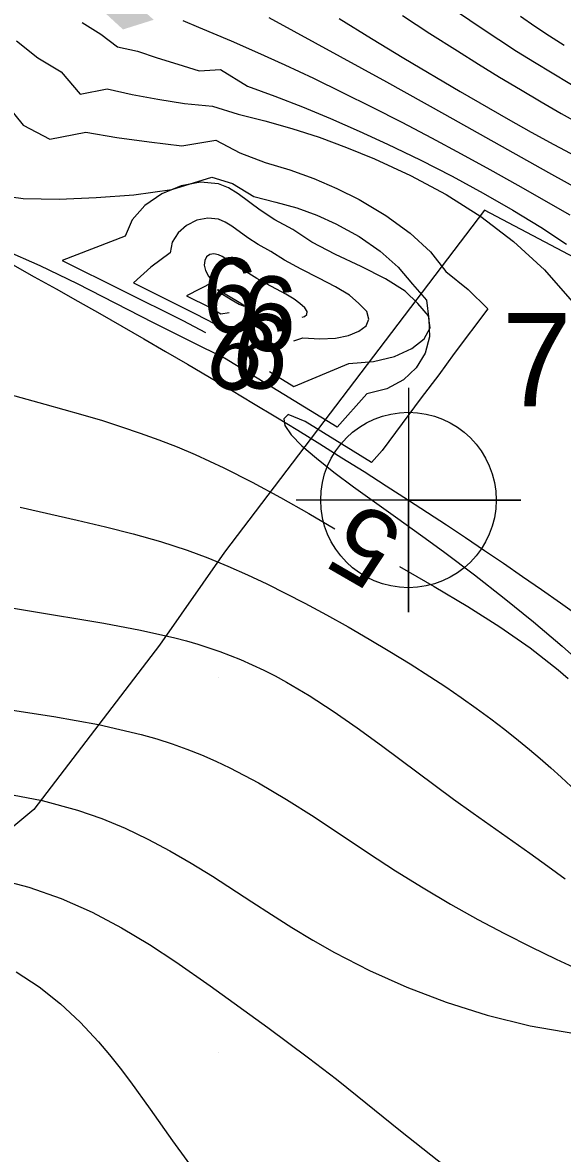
# Model space of a CAD drawing. Extents: x 2602990 to 2605851, y 618069 to 619180.
# Drawn here: x 2603794.76 to 2603809.18, y 618397.3 to 618427.51 of the extents above; entities that cross this region are included whole.
import ezdxf

# ---------------------------------------------------------------- set-up
doc = ezdxf.new("R2010")
doc.units = 0
for name, color, linetype in [('DTM Contours Major', 7, 'Continuous'), ('DTM Contours Major Text', 7, 'Continuous'), ('DTM Contours Minor', 7, 'Continuous'), ('DTM Contours Minor Text', 7, 'Continuous'), ('Exist DTM Breakline', 7, 'Continuous'), ('Exist DTM Breakline Cogo Number', 7, 'Continuous'), ('Exist DTM Breakline Cogo Point CELL', 7, 'Continuous'), ('Exist DTM Crownline', 7, 'Continuous'), ('Exist DTM QL2 LIDAR Elevation Point', 7, 'Continuous'), ('Exist Roads EOP', 7, 'Continuous'), ('PH Exist DTM Obscure Area', 7, 'Continuous'), ('PH Exist DTM Obscure Area Text', 7, 'Continuous')]:
    doc.layers.add(name, color=color, linetype=linetype)

# ---------------------------------------------------------------- blocks, each defined once
blk = doc.blocks.new('EXIST DTM BREAKLINE COGO POINT')
at = {"layer": 'Exist DTM Breakline Cogo Point CELL'}
blk.add_lwpolyline([(0, 0.06), (0, -0.06), (0, 0), (0.06, 0), (-0.06, 0)], dxfattribs=at)
blk.add_circle((0, 0), 0.04688, dxfattribs=at)

msp = doc.modelspace()

# ---------------------------------------------------------------- linework, layer by layer
at = {"layer": 'DTM Contours Major'}
for points in [[(2603804.913, 618427.699), (2603805.645, 618427.219), (2603806.379, 618426.751), (2603806.947, 618426.396), (2603807.509, 618426.051), (2603808.065, 618425.716), (2603808.614, 618425.391), (2603809.156, 618425.078), (2603809.691, 618424.776)], [(2603800.808, 618420.808), (2603800.612, 618420.92), (2603800.447, 618421.024), (2603800.192, 618421.198), (2603800.091, 618421.261), (2603800, 618421.305), (2603799.872, 618421.33), (2603799.763, 618421.308), (2603799.68, 618421.245), (2603799.63, 618421.148), (2603799.618, 618421.025), (2603799.652, 618420.882), (2603799.733, 618420.729), (2603799.858, 618420.57), (2603799.145, 618420.205), (2603799.771, 618419.893), (2603800.056, 618419.73), (2603800.281, 618419.763)], [(2603802.234, 618419.633), (2603802.294, 618419.654), (2603802.36, 618419.713), (2603802.367, 618419.791), (2603802.308, 618419.887), (2603802.171, 618420), (2603802.016, 618420.119), (2603801.799, 618420.25), (2603801.279, 618420.53), (2603801.025, 618420.671), (2603800.808, 618420.808)], [(2603793.152, 618409.343), (2603795.597, 618408.964), (2603796.793, 618408.751), (2603797.933, 618408.488), (2603798.351, 618408.368), (2603798.758, 618408.238), (2603799.155, 618408.095), (2603799.543, 618407.942), (2603799.924, 618407.776), (2603800.299, 618407.599), (2603801.065, 618407.196), (2603801.813, 618406.753), (2603802.55, 618406.284), (2603804.004, 618405.317), (2603804.728, 618404.844), (2603805.463, 618404.388), (2603806.197, 618403.956), (2603806.925, 618403.549), (2603807.642, 618403.168), (2603808.343, 618402.814), (2603809.023, 618402.486), (2603809.601, 618402.221)]]:
    msp.add_lwpolyline(points, dxfattribs=at)
at = {"layer": 'DTM Contours Minor'}
for points in [[(2603796.351, 618427.514), (2603796.855, 618427.195), (2603797.301, 618426.856), (2603797.837, 618426.748), (2603798.363, 618426.565), (2603798.912, 618426.394), (2603799.48, 618426.223), (2603800.053, 618426.25), (2603800.774, 618425.807), (2603801.499, 618425.544), (2603802.24, 618425.256), (2603802.992, 618424.944), (2603803.752, 618424.611), (2603804.515, 618424.259), (2603805.383, 618423.838), (2603806.238, 618423.401), (2603807.069, 618422.952), (2603807.864, 618422.497), (2603808.611, 618422.041), (2603809.299, 618421.589)], [(2603799.048, 618427.566), (2603799.46, 618427.386), (2603800.337, 618427.016), (2603801.039, 618426.709), (2603801.774, 618426.376), (2603802.534, 618426.019), (2603803.311, 618425.643), (2603804.099, 618425.251), (2603804.891, 618424.846), (2603805.689, 618424.426), (2603806.477, 618424.002), (2603807.246, 618423.579), (2603807.992, 618423.162), (2603809.382, 618422.369)], [(2603801.344, 618427.641), (2603804.49, 618425.922), (2603806.037, 618425.064), (2603808.817, 618423.501), (2603809.814, 618422.951)], [(2603803.225, 618427.614), (2603804.086, 618427.079), (2603804.946, 618426.559), (2603806.456, 618425.667), (2603807.736, 618424.929), (2603808.354, 618424.582), (2603808.957, 618424.251), (2603809.544, 618423.938)], [(2603806.406, 618427.781), (2603807.013, 618427.366), (2603807.488, 618427.052), (2603807.963, 618426.747), (2603808.438, 618426.45), (2603808.911, 618426.161), (2603809.384, 618425.879), (2603809.855, 618425.604), (2603810.337, 618425.33), (2603810.818, 618425.062), (2603811.3, 618424.802), (2603811.785, 618424.548), (2603812.273, 618424.301), (2603812.766, 618424.061), (2603813.348, 618423.791), (2603813.942, 618423.529), (2603814.556, 618423.276), (2603815.174, 618423.039)], [(2603808.064, 618427.677), (2603808.451, 618427.413), (2603808.842, 618427.156), (2603809.236, 618426.905)], [(2603794.598, 618427.02), (2603795.175, 618426.565), (2603795.795, 618426.191), (2603796.304, 618425.596), (2603797.025, 618425.739), (2603797.689, 618425.588), (2603798.38, 618425.462), (2603799.092, 618425.342), (2603799.835, 618425.276), (2603800.523, 618425.063), (2603801.235, 618424.886), (2603801.956, 618424.679), (2603802.685, 618424.442), (2603803.421, 618424.171), (2603804.164, 618423.867), (2603805.124, 618423.423), (2603806.076, 618422.912), (2603807.002, 618422.327), (2603807.883, 618421.661), (2603808.704, 618420.905), (2603809.446, 618420.052)], [(2603794.136, 618425.548), (2603794.778, 618424.764), (2603795.495, 618424.395), (2603796.45, 618424.583), (2603797.284, 618424.436), (2603798.144, 618424.321), (2603799.018, 618424.211), (2603799.925, 618424.363), (2603800.57, 618424.032), (2603801.245, 618423.773), (2603801.902, 618423.573), (2603802.542, 618423.341), (2603803.16, 618423.077), (2603803.753, 618422.782), (2603804.472, 618422.354), (2603805.115, 618421.883), (2603805.658, 618421.38), (2603806.074, 618420.856), (2603806.669, 618420.374), (2603807.192, 618419.864), (2603806.296, 618418.668), (2603805.882, 618418.095), (2603805.413, 618417.48), (2603804.908, 618416.795), (2603804.368, 618416.075), (2603804.084, 618415.758), (2603802.313, 618416.849), (2603801.863, 618417.033), (2603801.74, 618416.921), (2603801.767, 618416.74), (2603801.936, 618416.497), (2603802.227, 618416.202), (2603802.617, 618415.866), (2603803.083, 618415.497), (2603803.605, 618415.107), (2603804.786, 618414.258), (2603805.619, 618413.66), (2603806.041, 618413.351), (2603806.839, 618412.751), (2603807.632, 618412.131), (2603808.414, 618411.495), (2603809.175, 618410.849), (2603809.909, 618410.196)], [(2603793.871, 618422.93), (2603794.78, 618422.806), (2603795.739, 618422.787), (2603796.731, 618422.832), (2603797.737, 618422.903), (2603798.753, 618423.05), (2603799.823, 618423.378), (2603800.369, 618423.211), (2603800.942, 618422.858), (2603801.526, 618422.713), (2603802.086, 618422.556), (2603802.623, 618422.362), (2603803.135, 618422.134), (2603803.756, 618421.789), (2603804.314, 618421.397), (2603804.796, 618420.969), (2603805.184, 618420.515), (2603805.552, 618420.095), (2603805.616, 618419.576), (2603805.631, 618419.114), (2603805.516, 618418.678), (2603805.281, 618418.288), (2603804.936, 618417.965), (2603804.492, 618417.727), (2603803.961, 618417.593), (2603803.171, 618416.696), (2603800.162, 618418.546), (2603799.275, 618418.976), (2603798.265, 618419.482), (2603796.229, 618420.527), (2603795.231, 618421.011), (2603794.264, 618421.435)], [(2603801.981, 618421.981), (2603801.499, 618422.24), (2603801.114, 618422.492), (2603800.525, 618422.93), (2603800.268, 618423.092), (2603800, 618423.199), (2603799.52, 618423.241), (2603798.999, 618423.143), (2603798.486, 618422.928), (2603798.033, 618422.618), (2603797.689, 618422.236), (2603797.507, 618421.804), (2603795.825, 618421.154), (2603799.043, 618419.549), (2603799.653, 618419.224)], [(2603801.394, 618421.394), (2603801.054, 618421.582), (2603800.778, 618421.761), (2603800.353, 618422.066), (2603800.175, 618422.177), (2603800, 618422.252), (2603799.711, 618422.285), (2603799.417, 618422.225), (2603799.144, 618422.088), (2603798.917, 618421.887), (2603798.762, 618421.637), (2603798.703, 618421.353), (2603798.194, 618420.977), (2603797.73, 618420.557), (2603799.384, 618419.729), (2603799.9, 618419.455), (2603800.204, 618419.268)], [(2603801.361, 618418.183), (2603802.011, 618417.783), (2603803.478, 618418.395), (2603804.136, 618418.453), (2603804.701, 618418.59), (2603805.166, 618418.796), (2603805.495, 618419.055), (2603805.655, 618419.352), (2603805.61, 618419.672), (2603805.324, 618420), (2603804.988, 618420.333), (2603804.456, 618420.661), (2603803.809, 618420.987), (2603803.127, 618421.313), (2603802.491, 618421.644), (2603801.981, 618421.981)], [(2603802.007, 618419.008), (2603802.252, 618419.084), (2603802.704, 618419.055), (2603803.119, 618419.077), (2603803.469, 618419.146), (2603803.75, 618419.259), (2603803.94, 618419.408), (2603804.017, 618419.585), (2603803.96, 618419.785), (2603803.748, 618420), (2603803.5, 618420.222), (2603803.126, 618420.45), (2603802.677, 618420.683), (2603802.205, 618420.92), (2603801.76, 618421.157), (2603801.394, 618421.394)], [(2603800.221, 618420.221), (2603799.979, 618420.368), (2603799.972, 618420.368), (2603799.995, 618420.341), (2603800.106, 618420.255), (2603800.335, 618420.105), (2603800.549, 618419.987), (2603800.656, 618419.939), (2603800.684, 618419.934), (2603800.681, 618419.94), (2603800.595, 618420), (2603800.221, 618420.221)], [(2603793.33, 618417.87), (2603795.362, 618417.316), (2603796.376, 618417.029), (2603796.896, 618416.873), (2603797.407, 618416.711), (2603797.909, 618416.542), (2603798.404, 618416.363), (2603798.892, 618416.173), (2603799.376, 618415.969), (2603800.14, 618415.615), (2603800.897, 618415.229), (2603801.651, 618414.817), (2603802.407, 618414.388), (2603803.104, 618413.982)], [(2603794.697, 618414.563), (2603796.22, 618414.217), (2603796.976, 618414.038), (2603797.72, 618413.848), (2603798.449, 618413.641), (2603799.157, 618413.411), (2603799.709, 618413.208), (2603800.247, 618412.988), (2603800.773, 618412.755), (2603801.289, 618412.51), (2603801.797, 618412.255), (2603802.3, 618411.994), (2603802.882, 618411.681), (2603803.458, 618411.362), (2603804.024, 618411.038), (2603804.579, 618410.709), (2603805.121, 618410.376), (2603805.646, 618410.04), (2603806.07, 618409.759), (2603806.482, 618409.475), (2603806.882, 618409.191), (2603807.27, 618408.904), (2603807.647, 618408.617), (2603808.013, 618408.328), (2603808.307, 618408.088), (2603808.595, 618407.846), (2603808.876, 618407.601), (2603809.152, 618407.351), (2603809.422, 618407.095)], [(2603804.835, 618412.98), (2603805.761, 618412.446), (2603806.656, 618411.911), (2603807.518, 618411.364), (2603808.328, 618410.802), (2603809.072, 618410.219), (2603809.343, 618409.983)], [(2603793.87, 618411.972), (2603794.891, 618411.796), (2603796.934, 618411.461), (2603797.912, 618411.277), (2603798.834, 618411.069), (2603799.146, 618410.986), (2603799.449, 618410.898), (2603799.743, 618410.804), (2603800.03, 618410.706), (2603800.311, 618410.601), (2603800.585, 618410.49), (2603800.9, 618410.353), (2603801.209, 618410.206), (2603801.515, 618410.051), (2603801.818, 618409.886), (2603802.12, 618409.711), (2603802.423, 618409.528), (2603803.06, 618409.113), (2603803.703, 618408.667), (2603804.349, 618408.198), (2603806.28, 618406.763), (2603806.802, 618406.386), (2603808.316, 618405.316), (2603808.795, 618404.973), (2603809.259, 618404.633)], [(2603794.309, 618406.912), (2603795.287, 618406.722), (2603796.228, 618406.47), (2603796.881, 618406.244), (2603797.507, 618405.984), (2603798.111, 618405.695), (2603798.698, 618405.382), (2603799.271, 618405.05), (2603799.834, 618404.701), (2603800.884, 618404.02), (2603801.415, 618403.674), (2603801.957, 618403.33), (2603802.515, 618402.99), (2603803.094, 618402.66), (2603804.031, 618402.178), (2603805.026, 618401.734), (2603806.077, 618401.335), (2603807.179, 618400.991), (2603808.328, 618400.708), (2603809.521, 618400.496)], [(2603794.11, 618404.62), (2603794.934, 618404.41), (2603795.797, 618404.107), (2603796.621, 618403.74), (2603797.407, 618403.324), (2603798.153, 618402.877), (2603798.861, 618402.412), (2603799.776, 618401.772), (2603801.312, 618400.656), (2603802.405, 618399.848), (2603803.147, 618399.279), (2603803.706, 618398.834), (2603804.859, 618397.9), (2603805.453, 618397.425), (2603806.057, 618396.956)], [(2603794.595, 618402.148), (2603795.205, 618401.748), (2603795.774, 618401.296), (2603796.304, 618400.802), (2603796.794, 618400.278), (2603797.089, 618399.928), (2603797.371, 618399.572), (2603797.643, 618399.211), (2603798.169, 618398.478), (2603798.77, 618397.63), (2603799.465, 618396.675)]]:
    msp.add_lwpolyline(points, dxfattribs=at)
at = {"layer": 'Exist DTM Breakline'}
for points in [[(2603855.563, 618358.479), (2603862.541, 618379.668), (2603863.479, 618393.143), (2603859.324, 618404.705), (2603850.242, 618413.937), (2603817.732, 618430.625), (2603801.671, 618450.879), (2603791.4, 618462.329), (2603774.148, 618477.183)], [(2603751.583, 618450.596), (2603768.954, 618435.891), (2603805.072, 618414.752), (2603828.46, 618387.458), (2603819.191, 618359.408), (2603788.513, 618315.278), (2603769.845, 618293.995), (2603740.578, 618255.58)]]:
    msp.add_spline(points, degree=3, dxfattribs=at)
at = {"layer": 'Exist DTM Crownline'}
msp.add_spline([(2603233.488, 618380.754), (2603285.185, 618400.095), (2603335.457, 618418.629), (2603390.812, 618439.069), (2603440.087, 618457.325), (2603493.996, 618477.231), (2603542.655, 618495.301), (2603600.808, 618516.867), (2603653.659, 618536.362), (2603706.222, 618555.742), (2603764.811, 618577.593), (2603823.52, 618599.847), (2603878.564, 618620.56), (2603937.951, 618643.078), (2603997.369, 618665.789), (2604036.209, 618680.665), (2604055.311, 618688.017)], degree=3, dxfattribs=at)
at = {"layer": 'Exist DTM QL2 LIDAR Elevation Point'}
for p, q in [((2603800, 618420), (2603800, 618420)), ((2603800, 618410), (2603800, 618410)), ((2603800, 618400), (2603800, 618400))]:
    msp.add_line(p, q, dxfattribs=at)
at = {"layer": 'Exist Roads EOP'}
for points in [[(2603230.17, 618389.98), (2603282.929, 618409.597), (2603332.773, 618427.868), (2603388.167, 618448.413), (2603437.203, 618466.721), (2603490.778, 618486.527), (2603539.039, 618504.558), (2603597.451, 618526.156), (2603651.053, 618545.972), (2603705.208, 618566.084), (2603762.02, 618587.183), (2603820.334, 618609.162), (2603876.341, 618629.99), (2603934.909, 618652.28), (2603996.409, 618675.568), (2604033.216, 618689.957), (2604052.01, 618697.199)], [(2604034.633, 618668.486), (2603984.89, 618650.123), (2603936.767, 618631.654), (2603888.195, 618613.335), (2603837.766, 618594.258), (2603782.918, 618573.705), (2603731.939, 618554.39), (2603671.126, 618532.171), (2603621.822, 618514.106), (2603561.545, 618491.877), (2603506.421, 618471.293), (2603452.163, 618451.33), (2603398.364, 618431.316), (2603341.431, 618410.355), (2603281.65, 618388.199), (2603223.033, 618366.475), (2603185.717, 618352.612)]]:
    msp.add_spline(points, degree=3, dxfattribs=at)
at = {"layer": 'PH Exist DTM Obscure Area'}
msp.add_lwpolyline([(2603837.855, 618385.694), (2603832.954, 618392.809), (2603825.93, 618400.488), (2603821.248, 618409.017), (2603818.223, 618416.624), (2603807.105, 618422.493), (2603800.155, 618413.362), (2603798.42, 618410.873), (2603795.06, 618406.485), (2603785.045, 618398.142), (2603775.146, 618389.917), (2603762.364, 618387.068), (2603748.159, 618385.26), (2603736.641, 618385.012)], dxfattribs=at)

# ---------------------------------------------------------------- block references
at = {"layer": 'Exist DTM Breakline Cogo Point CELL', "xscale": 50, "yscale": 50}
msp.add_blockref('EXIST DTM BREAKLINE COGO POINT', (2603805.072, 618414.752), dxfattribs=at)

# ---------------------------------------------------------------- texts
at = {"layer": 'DTM Contours Major Text'}
msp.add_text('6', height=2, rotation=356.2039, dxfattribs=at).set_placement((2603800.535, 618418.784))
at = {"layer": 'DTM Contours Minor Text'}
msp.add_text('6', height=2, dxfattribs=at).set_placement((2603799.568, 618419.221))
for s, rotation, p in [('6', 328.6389, (2603799.431, 618418.193)), ('6', 351.7891, (2603800.265, 618417.847)), ('5', 149.9237, (2603805.035, 618414.017))]:
    msp.add_text(s, height=2, rotation=rotation, dxfattribs=at).set_placement(p)
at = {"layer": 'Exist DTM Breakline Cogo Number'}
msp.add_text('701', height=2.5, dxfattribs=at).set_placement((2603807.572, 618417.252))
at = {"layer": 'PH Exist DTM Obscure Area Text'}
msp.add_text('OBSCURED', height=6, rotation=17.4224, dxfattribs=at).set_placement((2603765.871, 618417.416))

doc.saveas('drawing.dxf')
